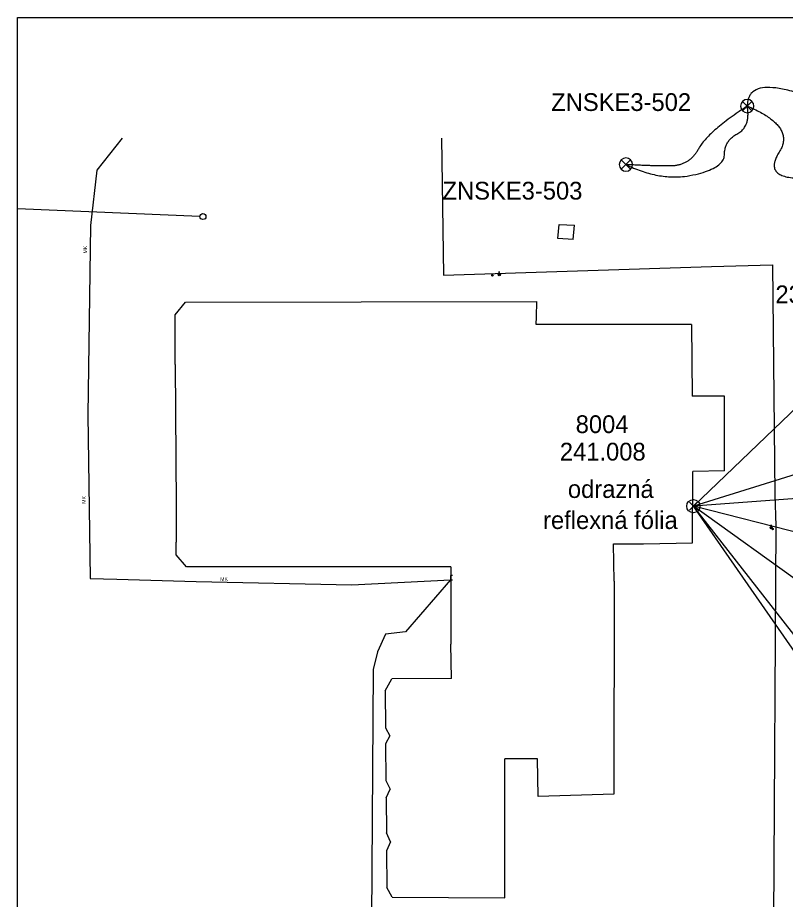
# Model space of a CAD drawing. Extents: x -264090 to -263500, y -1242327 to -1242030.
# Drawn here: x -264089.7 to -263959.9, y -1242178.7 to -1242029.6 of the extents above; entities that cross this region are included whole.
import ezdxf

# ---------------------------------------------------------------- set-up
doc = ezdxf.new("R2010")
doc.units = 0
for name, color, linetype in [('KFA_KOORD_SIT_a_IS_SEDA', 7, 'Continuous'), ('KFA_ZVS_BOD_CISLO', 7, 'Continuous'), ('KFA_ZVS_BOD_SYMBOL', 7, 'Continuous'), ('KFA_ZVS_BOD_VYSKA', 7, 'Continuous'), ('KFA_ZVS_NIVELACIA', 7, 'Continuous'), ('KFA_ZVS_POPIS', 7, 'Continuous'), ('KFA_ZVS_SMERY_A_DLZKY', 7, 'Continuous'), ('RAM_NA_TLAC', 7, 'Continuous')]:
    doc.layers.add(name, color=color, linetype=linetype)

msp = doc.modelspace()

# ---------------------------------------------------------------- linework, layer by layer
at = {"layer": 'KFA_KOORD_SIT_a_IS_SEDA'}
for p, q in [((-264072, -1242050), (-264076.26, -1242055.4)), ((-264018.04, -1242050), (-264017.72, -1242073.15)), ((-264076.26, -1242055.4), (-264077.35, -1242064.76)), ((-264058.85, -1242063.24), (-264089.66, -1242061.95)), ((-264077.35, -1242064.76), (-264077.8, -1242096.77)), ((-263998.36, -1242066.98), (-263998.17, -1242064.57)), ((-263998.17, -1242064.57), (-263995.59, -1242064.72)), ((-263995.79, -1242067.14), (-263995.59, -1242064.72)), ((-263995.79, -1242067.14), (-263998.36, -1242066.98)), ((-264017.72, -1242073.15), (-263972.45, -1242071.72)), ((-263972.45, -1242071.72), (-263962.12, -1242071.44)), ((-263962.12, -1242071.44), (-263961.71, -1242110.25)), ((-264008.43, -1242073.18), (-264008.14, -1242072.95)), ((-264008.41, -1242072.62), (-264008.16, -1242072.62)), ((-264008.29, -1242072.87), (-264008.29, -1242072.62)), ((-264063.06, -1242079.88), (-264061.28, -1242077.73)), ((-264061.28, -1242077.73), (-264001.95, -1242077.64)), ((-264002.01, -1242080.21), (-264001.95, -1242077.64)), ((-264063.05, -1242082.02), (-264063.06, -1242079.88)), ((-264002.04, -1242081.51), (-264002.01, -1242080.21)), ((-264063.02, -1242088.27), (-264063.05, -1242082.02)), ((-263975.78, -1242081.51), (-264002.04, -1242081.51)), ((-263975.78, -1242081.51), (-263975.68, -1242093.61)), ((-264063.02, -1242088.27), (-264062.89, -1242112.12)), ((-263970.24, -1242093.63), (-263975.68, -1242093.61)), ((-263970.22, -1242106.22), (-263970.24, -1242093.63)), ((-264077.8, -1242096.77), (-264077.43, -1242124.43)), ((-263975.61, -1242118.44), (-263975.57, -1242106.38)), ((-263970.22, -1242106.22), (-263975.57, -1242106.38)), ((-263961.71, -1242110.25), (-263961.58, -1242115.55)), ((-264062.89, -1242112.12), (-264062.88, -1242118.3)), ((-263962.48, -1242115.97), (-263962.19, -1242115.74)), ((-263962.46, -1242115.42), (-263962.21, -1242115.42)), ((-263962.34, -1242115.67), (-263962.34, -1242115.42)), ((-263961.58, -1242115.55), (-263962, -1242192.92)), ((-264062.88, -1242120.44), (-264062.88, -1242118.3)), ((-263989, -1242118.61), (-263983.93, -1242118.61)), ((-263988.88, -1242124.89), (-263989, -1242118.61)), ((-263983.93, -1242118.61), (-263975.61, -1242118.44)), ((-264061.11, -1242122.5), (-264062.88, -1242120.44)), ((-264016.48, -1242122.48), (-264061.11, -1242122.5)), ((-264016.48, -1242122.48), (-264016.47, -1242135.53)), ((-264016.21, -1242123.92), (-264016.51, -1242123.92)), ((-264016.51, -1242123.92), (-264016.5, -1242124.67)), ((-264077.43, -1242124.43), (-264072.89, -1242124.56)), ((-264072.89, -1242124.56), (-264059.47, -1242124.95)), ((-264059.47, -1242124.95), (-264033.2, -1242125.52)), ((-264033.2, -1242125.52), (-264016.5, -1242124.67)), ((-264016.5, -1242124.67), (-264024.13, -1242133.46)), ((-264016.5, -1242124.67), (-264016.2, -1242124.67)), ((-263988.88, -1242124.89), (-263988.91, -1242160.93)), ((-264027.51, -1242133.87), (-264028.85, -1242136.85)), ((-264024.13, -1242133.46), (-264027.51, -1242133.87)), ((-264016.38, -1242141.37), (-264016.47, -1242135.53)), ((-264028.85, -1242136.85), (-264029.59, -1242139.82)), ((-264029.59, -1242139.82), (-264029.91, -1242188.32)), ((-264027.55, -1242143.43), (-264026.42, -1242141.41)), ((-264016.38, -1242141.37), (-264026.42, -1242141.41)), ((-264027.55, -1242143.43), (-264027.5, -1242149.68)), ((-264027.5, -1242149.68), (-264026.79, -1242151.05)), ((-264026.79, -1242151.05), (-264027.48, -1242152.43)), ((-264027.48, -1242152.43), (-264027.43, -1242158.63)), ((-264007.37, -1242157.14), (-264007.36, -1242154.93)), ((-264001.8, -1242154.96), (-264007.36, -1242154.93)), ((-264001.73, -1242161.29), (-264001.8, -1242154.96)), ((-264007.34, -1242178.42), (-264007.37, -1242157.14)), ((-264027.43, -1242158.63), (-264026.72, -1242160.07)), ((-264027.41, -1242161.52), (-264026.72, -1242160.07)), ((-263988.91, -1242160.93), (-264001.73, -1242161.29)), ((-264027.41, -1242161.52), (-264027.36, -1242167.48)), ((-264026.65, -1242168.99), (-264027.36, -1242167.48)), ((-264026.65, -1242168.99), (-264027.34, -1242170.52)), ((-264027.34, -1242170.52), (-264027.29, -1242176.68)), ((-264026.37, -1242178.31), (-264027.29, -1242176.68)), ((-264026.37, -1242178.31), (-264007.34, -1242178.42))]:
    msp.add_line(p, q, dxfattribs=at)
for centre, radius in [((-264058.35, -1242063.26), 0.5), ((-264009.44, -1242073.2), 0.125), ((-264008.29, -1242073.06), 0.188), ((-263962.34, -1242115.86), 0.188), ((-263962.11, -1242116.08), 0.125)]:
    msp.add_circle(centre, radius, dxfattribs=at)
at = {"layer": 'KFA_ZVS_BOD_SYMBOL'}
for p, q in [((-263976.15, -1242112.87), (-263974.83, -1242111.54)), ((-263974.83, -1242112.87), (-263976.15, -1242111.54))]:
    msp.add_line(p, q, dxfattribs=at)
msp.add_circle((-263975.49, -1242112.21), 1.12, dxfattribs=at)
at = {"layer": 'KFA_ZVS_NIVELACIA'}
for p, q in [((-263967.17, -1242045.37), (-263967.17, -1242045.37)), ((-263965.58, -1242045.37), (-263965.58, -1242045.37)), ((-263965.58, -1242045.37), (-263965.58, -1242045.37)), ((-263987.68, -1242055.26), (-263987.68, -1242055.26)), ((-263986.09, -1242055.26), (-263986.09, -1242055.26)), ((-263986.09, -1242055.26), (-263986.09, -1242055.26))]:
    msp.add_line(p, q, dxfattribs=at)
for points in [[(-263967.17, -1242045.37), (-263966.38, -1242044.57), (-263967.17, -1242043.78)], [(-263965.58, -1242043.78), (-263966.38, -1242044.57), (-263965.58, -1242045.37)], [(-263965.58, -1242043.78), (-263966.38, -1242044.57), (-263965.58, -1242045.37)], [(-263987.68, -1242055.26), (-263986.88, -1242054.47), (-263987.68, -1242053.67)], [(-263986.09, -1242053.67), (-263986.88, -1242054.47), (-263986.09, -1242055.26)], [(-263986.09, -1242053.67), (-263986.88, -1242054.47), (-263986.09, -1242055.26)]]:
    msp.add_lwpolyline(points, dxfattribs=at)
for centre, start, end in [((-263966.38, -1242044.57), 45, 135), ((-263966.38, -1242044.57), 135, 225), ((-263966.38, -1242044.57), 315, 45), ((-263966.38, -1242044.57), 315, 45), ((-263966.38, -1242044.57), 225, 315), ((-263986.88, -1242054.47), 135, 225), ((-263986.88, -1242054.47), 45, 135), ((-263986.88, -1242054.47), 315, 45), ((-263986.88, -1242054.47), 315, 45), ((-263986.88, -1242054.47), 225, 315)]:
    msp.add_arc(centre, 1.12, start, end, dxfattribs=at)
for points in [[(-263940.79, -1242078.94), (-263934.16, -1242061.1), (-263943.4, -1242047.98), (-263966.38, -1242038.9), (-263966.38, -1242044.57)], [(-263966.38, -1242044.57), (-263973.1, -1242048.95), (-263976.16, -1242054.7), (-263982.74, -1242054.7), (-263986.88, -1242054.47)], [(-263986.88, -1242054.47), (-263980.88, -1242057.38), (-263970.23, -1242055.07), (-263970.23, -1242050.43), (-263965.78, -1242048.02), (-263966.38, -1242044.57)], [(-263966.38, -1242044.57), (-263958.15, -1242047.98), (-263963.82, -1242056.78), (-263950.49, -1242056.78), (-263940.96, -1242064.52), (-263940.79, -1242078.94)]]:
    msp.add_open_spline(points, degree=2, dxfattribs=at)
at = {"layer": 'KFA_ZVS_SMERY_A_DLZKY'}
for p in [(-263854.01, -1242074.33), (-263940.79, -1242078.94), (-263779.17, -1242098.02), (-263936.8, -1242167.95), (-263786.21, -1242248.09), (-263858.27, -1242262.29), (-263768, -1242165.53)]:
    msp.add_line(p, (-263975.49, -1242112.21), dxfattribs=at)
at = {"layer": 'RAM_NA_TLAC'}
msp.add_lwpolyline([(-264089.66, -1242029.62), (-263499.66, -1242029.62), (-263499.66, -1242326.62), (-264089.66, -1242326.62)], close=True, dxfattribs=at)

# ---------------------------------------------------------------- texts
at = {"layer": 'KFA_KOORD_SIT_a_IS_SEDA'}
for p in [(-264077.94, -1242069.5), (-264078.15, -1242111.8)]:
    msp.add_text('MK', height=0.625, rotation=90, dxfattribs=at).set_placement(p)
msp.add_text('MK', height=0.625, dxfattribs=at).set_placement((-264055.42, -1242124.85))
at = {"layer": 'KFA_ZVS_BOD_CISLO'}
for s, p in [('ZNSKE3-502', (-263999.51, -1242045.4)), ('ZNSKE3-503', (-264017.87, -1242060.38)), ('8004', (-263995.37, -1242099.86))]:
    msp.add_text(s, height=3, dxfattribs=at).set_placement(p)
at = {"layer": 'KFA_ZVS_BOD_VYSKA'}
for s, p in [('237.930', (-263961.62, -1242077.9)), ('241.008', (-263998.05, -1242104.5))]:
    msp.add_text(s, height=3, dxfattribs=at).set_placement(p)
at = {"layer": 'KFA_ZVS_POPIS'}
for s, p in [('odrazná', (-263996.69, -1242110.83)), ('reflexná fólia', (-264000.88, -1242116.08))]:
    msp.add_text(s, height=3, dxfattribs=at).set_placement(p)

doc.saveas('drawing.dxf')
